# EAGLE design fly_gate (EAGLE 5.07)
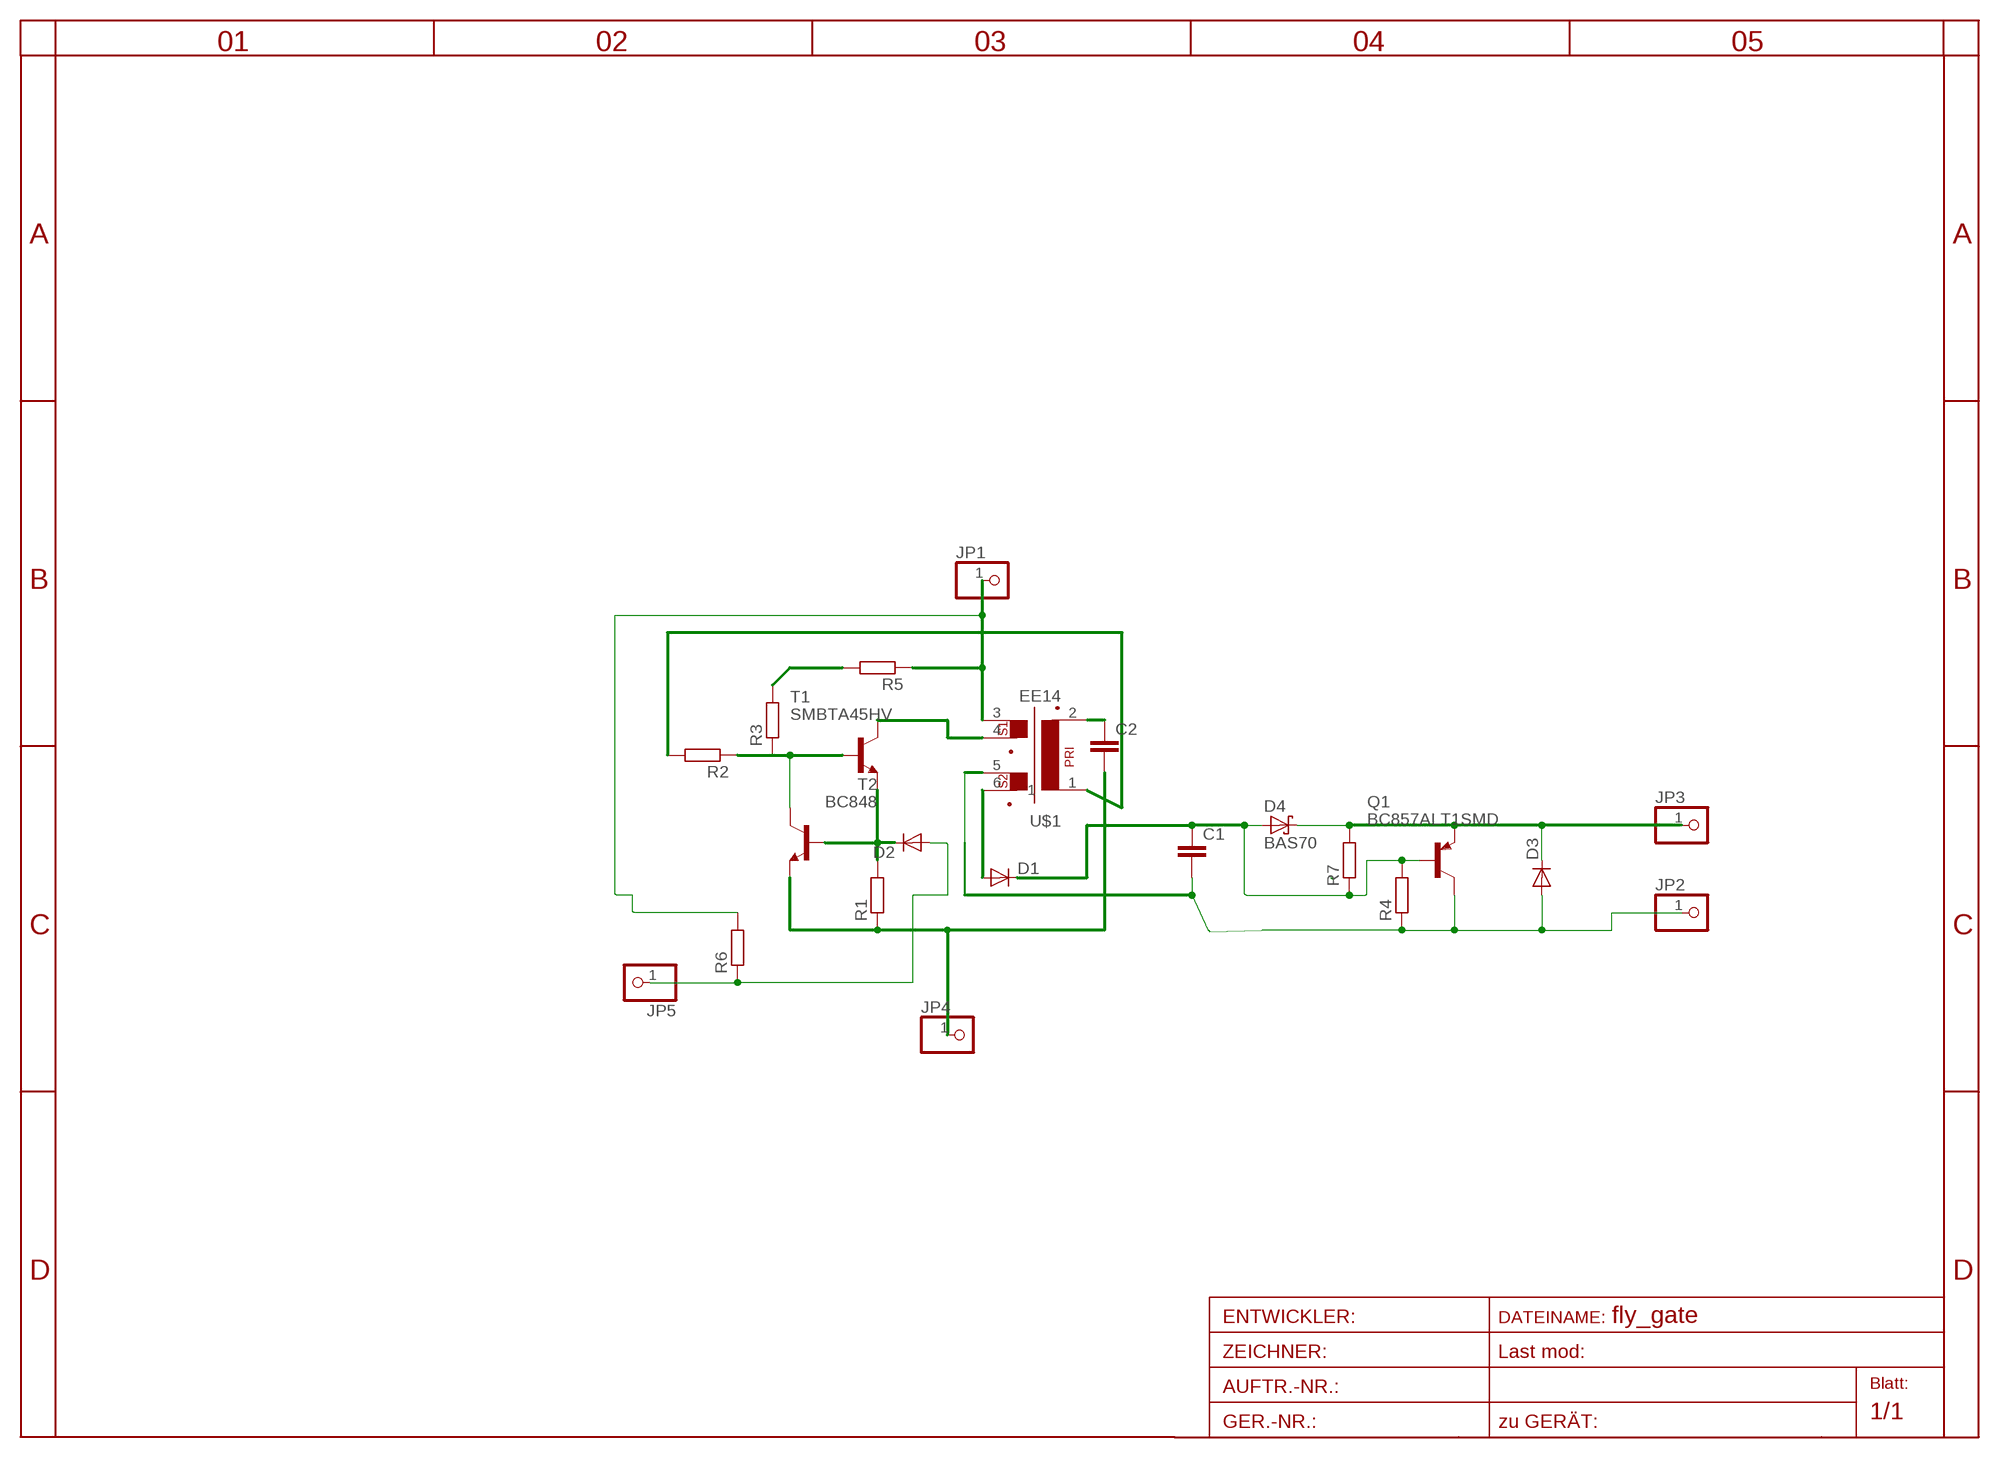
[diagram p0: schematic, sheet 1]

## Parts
C1  C-EUC0805  [C0805]
C2  C-EUC0805  [C0805]
D1  DIODE-SMA-DO214  [SMA-DO214AC]
D2  DIODE-MINIMELF  [MINIMELF]
D3  DIODE-MINIMELF  [MINIMELF]
D4  BAS70  [SOT23]
JP1  PINHD-1X11MM6  [1X1MM8]
JP2  PINHD-1X11MM6  [1X1MM8]
JP3  PINHD-1X11MM6  [1X1MM8]
JP4  PINHD-1X11MM6  [1X1MM8]
JP5  PINHD-1X11MM6  [1X1MM8]
Q1  BC857ALT1SMD  [SOT23-BEC]
R1  R-EU_R1206  [R1206]
R2  R-EU_R0805  [R0805]
R3  R-EU_R1206  [R1206]
R4  R-EU_R0805  [R0805]
R5  R-EU_R1206  [R1206]
R6  R-EU_R1206  [R1206]
R7  R-EU_R0805  [R0805]
T1  SMBTA45HV  [SOT23HV]
T2  BC848  [SOT23]
U$1  EE14  [EE14]

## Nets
A: D1.A U$1.6
B1C2: R2.1 R3.1 T1.1(B) T2.C
C1: T1.3(C) U$1.4
EB: D2.C R1.2 T1.2(E) T2.B
N$1: R3.2 R5.2
N$2: D2.A JP5.1 R6.1
N$4: R2.2 U$1.1
N$5: D3.C D4.3(C) JP3.1 Q1.E R7.2
N$6: C2.1 U$1.2
NDOT: C1.2 D3.A JP2.1 Q1.C R4.1 U$1.5
V+: JP1.1 R5.1 R6.2 U$1.3
V-: C2.2 JP4.1 R1.1 T2.E
VOUT+: C1.1 D1.K(C) D4.1(A) Q1.B R4.2 R7.1

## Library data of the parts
C1 C2 = rcl:C-EU: CAPACITOR, European symbol
D1-D3 = diode:DIODE-: DIODE
D4 = diode:BAS70: Silicon Schottky Diodes
JP1-JP5 = pinhead:PINHD-1X1: PIN HEADER
Q1 = transistor-pnp:BC857*: PNP Transistror
R1-R7 = rcl:R-EU_: RESISTOR, European symbol
T1 = transistor-npn:SMBTA45
T2 = transistor:BC848: NPN TRANSISTOR
U$1 = trafo:EE14

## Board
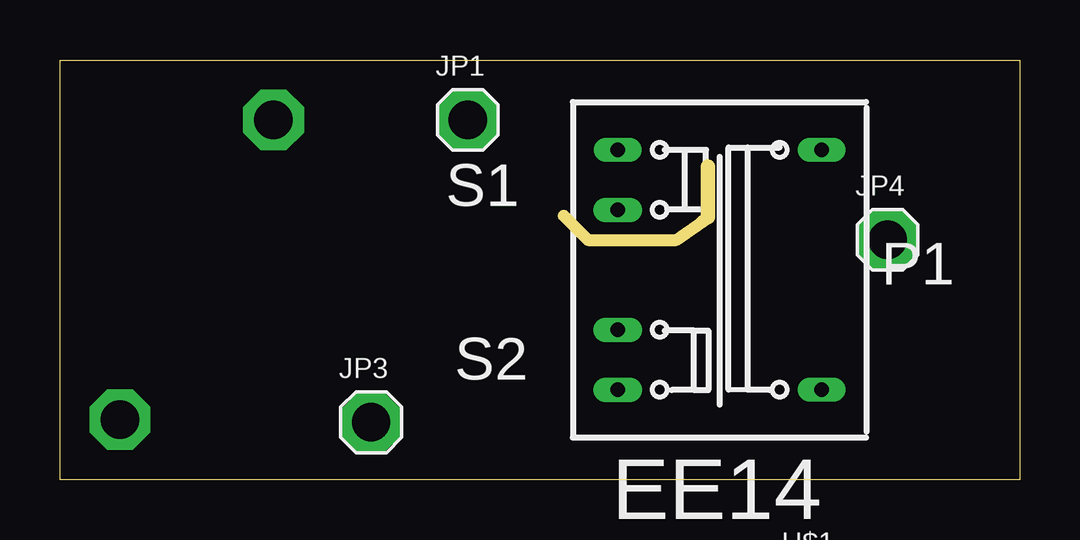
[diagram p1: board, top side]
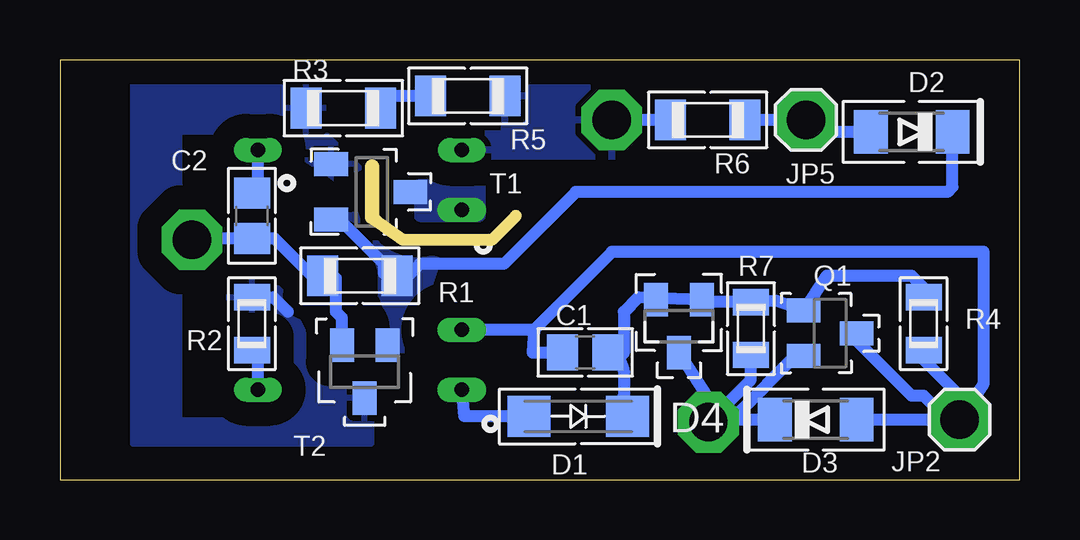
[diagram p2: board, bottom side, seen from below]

Size 40 x 17.5 mm. Coordinates in mm from the lower left corner, seen from the top.
Outline: 0,17.5 40,17.5 40,0 0,0 0,17.5
Copper layers (1*16): Top 0.035mm / dielectric 1.5mm / Bottom 0.035mm
Design rules "default *": minimum track width 10mil, minimum drill 20mil, track to track 8mil, track to pad 8mil, pad to pad 8mil, via to via 8mil, smd to smd 8mil, copper to edge 40mil, drill to drill 8mil, minimum pad ring 1mil, minimum via ring 8mil, stop-mask expansion 4mil, vias tented up to drill 0mil, thermal gap 10mil
Milling: 5 lines

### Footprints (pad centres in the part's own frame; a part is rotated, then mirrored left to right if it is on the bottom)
C0805 = smd 1.3 x 1.5: 1 -0.95,0; 2 0.95,0
SMA-DO214AC = smd 1.8 x 1.7: A 2.05,-0.127; K -2.05,-0.127
MINIMELF = smd 1.4 x 1.8: A 1.7,0; C -1.7,0
SOT23 = smd 1 x 1.4: 1 -0.95,-1.1; 2 0.95,-1.1; 3 0,1.1
1X1MM8 = drill 1.6 pad 2.54 octagon: 1 0,0
SOT23-BEC = smd 1 x 1.4: B -0.95,-1.1; C 0,1.1; E 0.95,-1.1
R1206 = smd 1.3 x 1.7: 1 -1.55,0; 2 1.55,0
R0805 = smd 1.1 x 1.5: 1 -1.1,0; 2 1.1,0
SOT23HV = smd 1 x 1.4: 1 -1.15,-1.7; 2 1.15,-1.7; 3 0,1.6
SOT23' = smd 1 x 1.4: B -0.95,-1.1; C 0,1.1; E 0.95,-1.1
EE14 = drill 0.6 pad 1 long: 1 4.25,-5; 2 4.25,5; 3 -4.25,5 | drill 0.6 pad 1.016 long: 4 -4.25,2.5; 5 -4.25,-2.5; 6 -4.25,-5

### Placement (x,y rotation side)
C1  18.11,5.3 180 bottom
C2  32,11 270 bottom
D1  18.39,2.51 180 bottom
D2  4.5,14.5 180 bottom
D3  8.5,2.5 0 bottom
D4  14.2,6.4 180 bottom
JP1  17,15 0 top
JP2  2.5,2.5 0 bottom
JP3  12.97,2.39 0 top
JP4  34.5,10 0 top
JP5  8.9,15 0 bottom
Q1  7.9,6.1 270 bottom
R1  27.5,8.5 0 bottom
R2  32,6.5 270 bottom
R3  28.19,15.49 0 bottom
R4  4,6.5 90 bottom
R5  23,16 180 bottom
R6  13,15 180 bottom
R7  11.2,6.3 270 bottom
T1  27,12 270 bottom
T2  BC848  [SOT23']  27.3,4.5 180 bottom
U$1  27.5,8.75 0 top

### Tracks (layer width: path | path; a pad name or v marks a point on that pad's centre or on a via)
A
  Bottom 0.5: D1.A 23.14,2.64 U$1.6
B1C2
  Bottom 0.5: R2.1 31.1,7.6 30.5,7
  pour Bottom (isolate 1, rank 3): 29,16.5 37,16.5 37,1.5 27,1.5 27,4.5 28.5,4.5 29.5,5.5 31,8.5 33,8.5 33,2.5 35,2.5 35,14.5 31.5,14.5 28.5,12.5 27.5,13 29,14.5
C1
  pour Bottom (isolate 1, rank 3, no thermals): 22.5,12.3 25,12.3 25,11 22.5,11
EB
  Bottom 0.5: D2.C 2.8,12.2 3,12 18.5,12 21.5,9 25,9 25.5,8.5 R1.2 26.5,8.6 26.5,9 28.2,10.7 T1.2
  pour Bottom (isolate 1.5, rank 3, no thermals): 25.5,5 25.5,6.5 25,7 24.2,9.3 arc113 27.5,11.5 29,11.5 29,10.5 27.5,10 27,9.5 27,5.5 26.5,5
N$1
  Bottom 0.5: R5.2 26.13,16 R3.2
N$2
  Bottom 0.5: R6.1 JP5.1 8,14.5 D2.A
N$4
  Bottom 0.5: U$1.1 31.75,5.15 R2.2
N$5
  Bottom 0.5: R7.2 11.2,4.16 JP3.1 | D4.3 13,3.42 JP3.1 | D3.C 12,2.5 | 12,2.5 12.86,2.5 JP3.1 | Q1.E 9.1,5.4 12,2.5
N$6
  Bottom 0.5: U$1.2 31.75,12.2 C2.1
NDOT
  Bottom 0.5: 20.25,6.25 U$1.5 | 20.25,6.25 17,9.5 1.5,9.5 1.5,4 JP2.1 | JP2.1 3,2.5 | 3,2.5 D3.A | Q1.C 6.9,5.9 4.5,3.5 4,3.5 3,2.5 | R4.1 4,5 2.5,3.5 JP2.1 | C1.2 20.3,5.3 20.25,6.25
V+
  Bottom 0.5: R6.2 JP1.1
  pour Bottom (isolate 1, rank 4): 17.5,16.5 20.5,16.5 21.6,16.4 21.5,14.5 21.6,14.4 22.6,14.4 23,13.5 16.5,13.5
V-
  Bottom 0.5: T2.E 28.25,6.75 28.5,7 28.5,8.4 R1.1 29.5,8.5 31.05,10.05 C2.2 34.45,10.05 JP4.1
VOUT+
  Bottom 0.5: 16.69,5.09 16.5,4.54 16.5,3.5 16.84,2.85 D1.K 16.6,2.39 | 16.69,5.09 C1.1 | R4.2 4,8 4.5,8.5 8.05,8.5 Q1.B 10.15,7.45 R7.1 12.85,7.4 D4.1 15.9,7.6 16.5,7 16.5,5.28 16.69,5.09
